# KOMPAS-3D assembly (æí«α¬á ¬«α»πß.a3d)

Referenced files in D:\МОДЕЛЬ ТАНКА Т90\ПОДСБОРКИ\КОРПУС\: Сборка дно с пластиком.a3d, Сборка борт левый с пластиком.a3d, Сборка борт правый с пластиком.a3d, Сборка корпус лоб.a3d, Сборка корпус верх.a3d, Сборка корма.a3d, Сборка корма верх.a3d, Сборка крышка моторного.a3d
Referenced files in D:\МОДЕЛЬ ТАНКА Т90\ДЕТАЛИ\КОРПУС\МЕТАЛЛ\КОРПУС ЛИТОЙ\: перемычка корпуса.m3d, дно1скос.m3d, дно2 скос .m3d, тяга отвала.m3d, отвал.m3d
